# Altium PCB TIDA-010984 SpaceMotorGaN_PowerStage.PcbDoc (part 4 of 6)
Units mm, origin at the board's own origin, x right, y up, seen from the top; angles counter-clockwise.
Board outline 177.8 x 152.4 mm, 8 copper layers (Top Layer, DC LINK Layer 2, GND Layer 3, 3V3 Layer 4, Layer 5, Layer 6, GND Layer 7, Bottom Layer), stack 1.554 mm thick; 582 components, 280 nets, 1847 pads, 979 vias.
Unrouted connection lines stored in the file: 474.
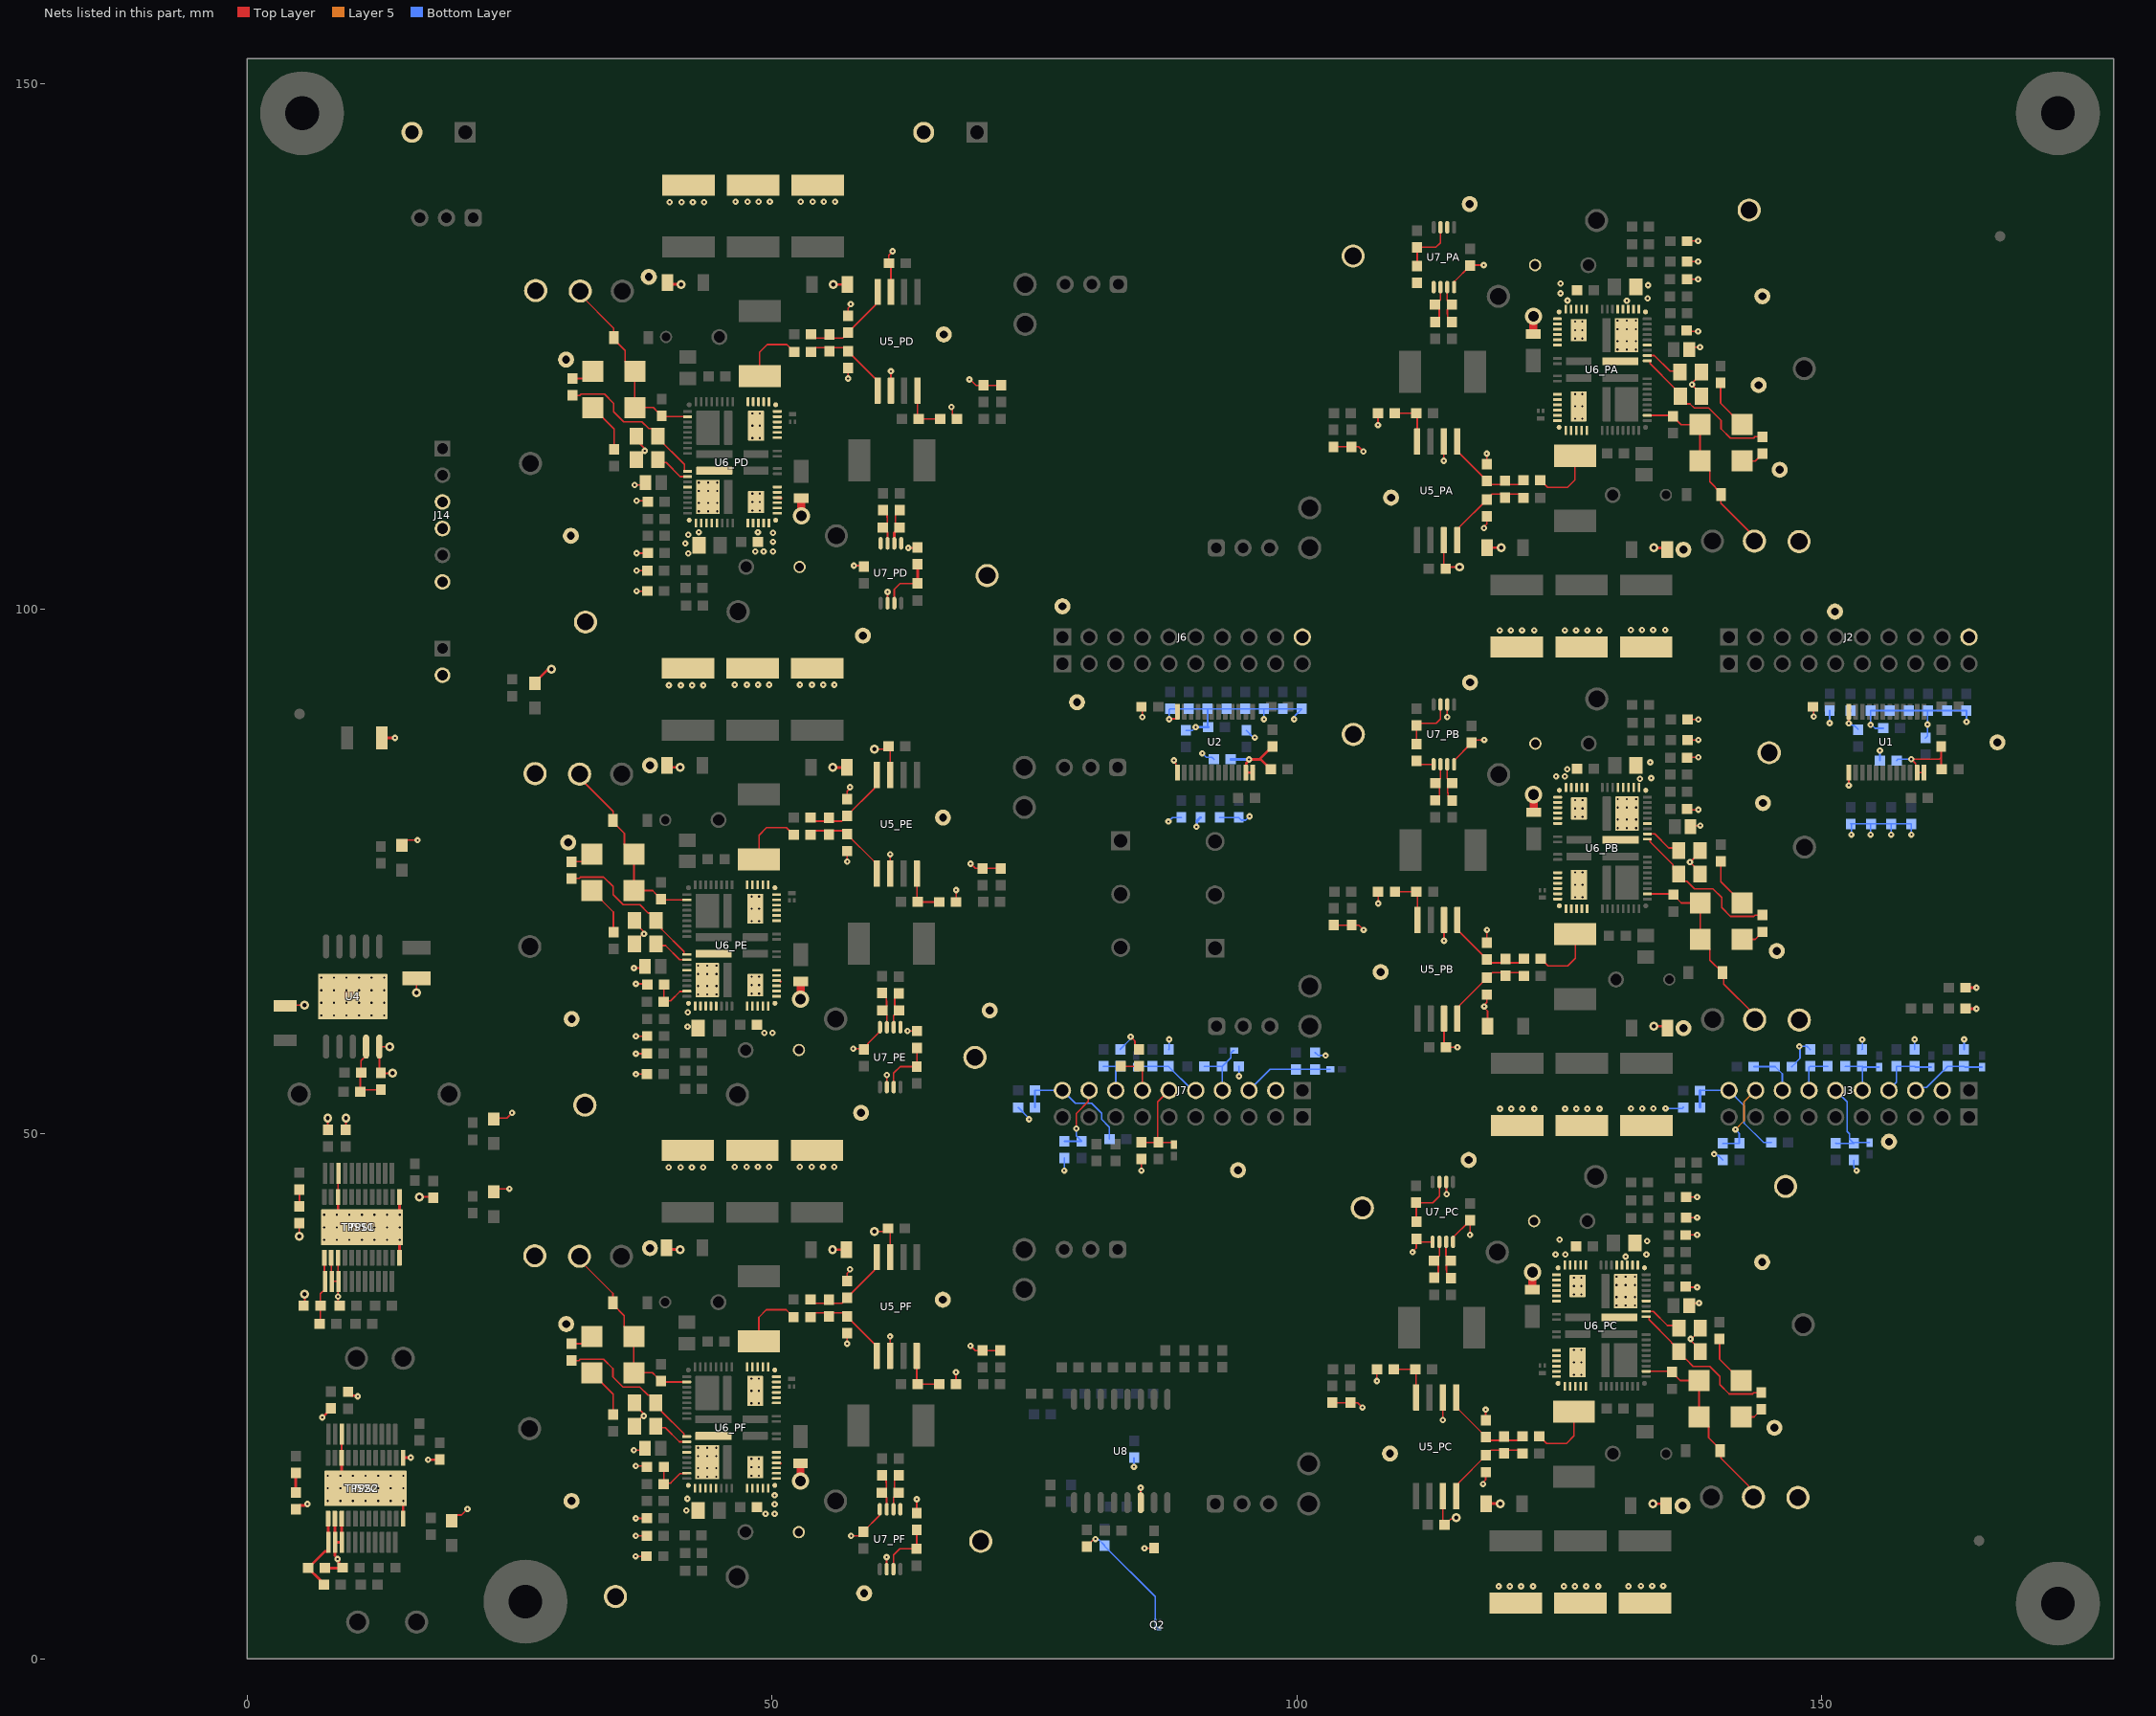
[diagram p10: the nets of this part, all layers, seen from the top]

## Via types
v1: diameter 0.61, hole 0.2, Top Layer to Bottom Layer, tented both sides, 306 vias
v2: diameter 0.61, hole 0.203, Top Layer to Bottom Layer, tented both sides, 272 vias
v3: diameter 0.5, hole 0.2, Top Layer to Bottom Layer, tented both sides, 216 vias
v4: diameter 0.5, hole 0.2, Top Layer to Bottom Layer, 66 vias
v5: diameter 0.61, hole 0.2, Top Layer to Bottom Layer, 61 vias
v6: diameter 0.864, hole 0.406, Top Layer to Bottom Layer, tented both sides, 17 vias
v7: diameter 1.651, hole 1.016, Top Layer to Bottom Layer, tented both sides, 12 vias
v8: diameter 0.864, hole 0.406, Top Layer to Bottom Layer, 9 vias
v9: diameter 0.61, hole 0.203, Top Layer to Bottom Layer, 8 vias
v10: diameter 1.27, hole 0.711, Top Layer to Bottom Layer, tented both sides, 5 vias
v11: diameter 0.61, hole 0.2, Top Layer to Bottom Layer, tented top, 2 vias
v12: diameter 1.651, hole 1.016, Top Layer to Bottom Layer, 2 vias
v13: diameter 0.61, hole 0.203, Top Layer to Bottom Layer, tented bottom, 1 vias
v14: diameter 1.27, hole 0.711, Top Layer to Bottom Layer, 1 vias
v15: diameter 1.651, hole 1.016, Top Layer to Bottom Layer, tented top, 1 vias

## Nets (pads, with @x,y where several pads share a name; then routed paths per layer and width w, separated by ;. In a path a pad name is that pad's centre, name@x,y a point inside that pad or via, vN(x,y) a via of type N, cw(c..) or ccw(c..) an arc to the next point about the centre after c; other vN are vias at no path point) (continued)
EN_HI_PE: C48_PE.1 R82_PE.1 U6_PE.18 | length 4.3
  Top Layer w0.152: C48_PE.1@39.723,64.204 R82_PE.1@39.723,62.592 ; R82_PE.1@39.732,62.576 R82_PE.1@39.707,62.576 R82_PE.1@39.723,62.592 ; U6_PE.18@41.898,63.597 41.866,63.566 41.244,63.566 40.4,62.722 40.4,62.665 39.795,62.665 R82_PE.1@39.723,62.592
EN_HI_PF: C48_PF.1 R82_PF.1 U6_PF.18 | length 4.3
  Top Layer w0.152: C48_PF.1@39.709,18.28 R82_PF.1@39.709,16.668 ; R82_PF.1@39.718,16.652 R82_PF.1@39.693,16.652 R82_PF.1@39.709,16.668 ; U6_PF.18@41.884,17.673 41.853,17.642 41.23,17.642 40.387,16.798 40.387,16.74 39.781,16.74 R82_PF.1@39.709,16.668
FB3: R69.1 R71.2 TPS2.13 TPS2C.12 | length 7.9
  Top Layer w0.254: R71.2@5.804,8.646 R71.2@5.829,8.646 ; R69.1@7.327,7.069 7.302,7.069 6.954,7.417 6.954,7.52 R71.2@5.829,8.646 ; TPS2.13@7.717,13.34 7.726,13.331 7.726,10.303 7.645,10.222 7.405,10.222 R71.2@5.829,8.646
FB5: R61.1 R63.2 TPS1.13 TPS1C.12 | length 6.5
  Top Layer w0.152: R61.1@6.912,31.892 6.988,31.969 R63.2@6.988,33.642 6.988,34.772 7.387,35.171 7.387,35.953 7.377,35.963 7.377,38.189 TPS1.13@7.368,38.198
GND: C1.2 C2.2 C3.2 C4.2 C5.2 C6.2 C7.2 C8.2 C9.2 C10.2 C11.2 C12.2 C13.2 C14.2 C15.2 C16.2 C17.2 C18.2 C19.2 C20.2 C22.2 C23.2 C24.2 C25.2 C27.2 C28.2 C30.2 C31_PA.2 C31_PB.2 C31_PC.2 C31_PD.2 C31_PE.2 C31_PF.2 C35_PA.2 C35_PB.2 C35_PC.2 C35_PD.2 C35_PE.2 C35_PF.2 C36_PA.2 C36_PB.2 C36_PC.2 C36_PD.2 C36_PE.2 C36_PF.2 C37_PA.1 C37_PB.1 C37_PC.1 C37_PD.1 C37_PE.1 C37_PF.1 C38_PA.2 C38_PB.2 C38_PC.2 C38_PD.2 C38_PE.2 C38_PF.2 C39_PA.2 C39_PB.2 C39_PC.2 C39_PD.2 C39_PE.2 C39_PF.2 C40_PA.2 C40_PB.2 C40_PC.2 C40_PD.2 C40_PE.2 C40_PF.2 C42_PA.2 C42_PB.2 C42_PC.2 C42_PD.2 C42_PE.2 C42_PF.2 C43_PA.2 C43_PB.2 C43_PC.2 C43_PD.2 C43_PE.2 C43_PF.2 C44_PA.1 C44_PB.1 C44_PC.1 C44_PD.1 C44_PE.1 C44_PF.1 C46_PA.1 C46_PB.1 C46_PC.1 C46_PD.1 C46_PE.1 C46_PF.1 C48_PA.2 C48_PB.2 C48_PC.2 C48_PD.2 C48_PE.2 C48_PF.2 C49_PA.2 C49_PB.2 C49_PC.2 C49_PD.2 C49_PE.2 C49_PF.2 C50_PA.1 C50_PB.1 C50_PC.1 C50_PD.1 C50_PE.1 C50_PF.1 C51_PA.1 C51_PB.1 C51_PC.1 C51_PD.1 C51_PE.1 C51_PF.1 C52_PA.1 C52_PB.1 C52_PC.1 C52_PD.1 C52_PE.1 C52_PF.1 C53_PA.2 C53_PB.2 C53_PC.2 C53_PD.2 C53_PE.2 C53_PF.2 C56_PA.1 C56_PB.1 C56_PC.1 C56_PD.1 C56_PE.1 C56_PF.1 C57.1 C61.2 D10.2 D12.2 D13.2 D14.2 D15_PA.2 D15_PB.2 D15_PC.2 D15_PD.2 D15_PE.2 D15_PF.2 D17.2 J2.10 J3.2 J6.10 J7.2 J11.2 J13.2 J14.3 J14.4 J14.6 J15.2 pad.8 pad.9 pad.10 pad.11 pad.12 pad.13 R13.1 R15.1 R16.1 R17.1 R18.1 R19.1 R20.1 R21.1 R22.1 R23.1 R24.1 R25.1 R26.1 R27.1 R28.1 R39.1 R40.1 R41.1 R42.1 R43.1 R44.1 R45.1 R46.1 R47.1 R48.1 R49.1 R50.1 R51.1 R52.1 R53.1 R57.1 R58.1 R60.1 R62.1 R63.1 R66.1 R68.1 R70.1 R71.1 R74.1 R86_PA.2 R86_PB.2 R86_PC.2 R86_PD.2 R86_PE.2 R86_PF.2 R91_PA.2 R91_PB.2 R91_PC.2 R91_PD.2 R91_PE.2 R91_PF.2 R92_PA.1 R92_PB.1 R92_PC.1 R92_PD.1 R92_PE.1 R92_PF.1 R95_PA.1 R95_PB.1 R95_PC.1 R95_PD.1 R95_PE.1 R95_PF.1 R100.2 TP14_PA.2 TP14_PB.2 TP14_PC.2 TP14_PD.2 TP14_PE.2 TP14_PF.2 TP16_PA.1 TP16_PB.1 TP16_PC.1 TP16_PD.1 TP16_PE.1 TP16_PF.1 TP17_PA.1 TP17_PB.1 TP17_PC.1 TP17_PD.1 TP17_PE.1 TP17_PF.1 TP18_PA.1 TP18_PB.1 TP18_PC.1 TP18_PD.1 TP18_PE.1 TP18_PF.1 TPS1.1 TPS1.10 TPS1.14 TPS1.15 TPS1.24 TPS1.25 TPS1C.9 TPS1C.13 TPS1C.14 TPS2.1 TPS2.10 TPS2.14 TPS2.15 TPS2.24 TPS2.25 TPS2C.9 TPS2C.13 TPS2C.14 U1.12 U1.13 U2.12 U2.13 U4.10 U4.11 U5_PA.2 U5_PA.7 U5_PB.2 U5_PB.7 U5_PC.2 U5_PC.7 U5_PD.2 U5_PD.7 U5_PE.2 U5_PE.7 U5_PF.2 U5_PF.7 U6_PA.14 U6_PA.20 U6_PA.21 U6_PA.22 U6_PA.23 U6_PA.24 U6_PA.25 U6_PA.29 U6_PA.30 U6_PA.31 U6_PA.32 U6_PA.33 U6_PA.34 U6_PA.35 U6_PA.36 U6_PA.37 U6_PA.38 U6_PA.39 U6_PA.40 U6_PA.67 U6_PA.68 U6_PA.70 U6_PB.14 U6_PB.20 U6_PB.21 U6_PB.22 U6_PB.23 U6_PB.24 U6_PB.25 U6_PB.29 U6_PB.30 U6_PB.31 U6_PB.32 U6_PB.33 U6_PB.34 U6_PB.35 U6_PB.36 U6_PB.37 U6_PB.38 U6_PB.39 U6_PB.40 U6_PB.67 U6_PB.68 U6_PB.70 U6_PC.14 U6_PC.20 U6_PC.21 U6_PC.22 U6_PC.23 U6_PC.24 U6_PC.25 U6_PC.29 U6_PC.30 U6_PC.31 U6_PC.32 U6_PC.33 U6_PC.34 U6_PC.35 U6_PC.36 U6_PC.37 U6_PC.38 U6_PC.39 U6_PC.40 U6_PC.67 U6_PC.68 U6_PC.70 U6_PD.14 U6_PD.20 U6_PD.21 U6_PD.22 U6_PD.23 U6_PD.24 U6_PD.25 U6_PD.29 U6_PD.30 U6_PD.31 U6_PD.32 U6_PD.33 U6_PD.34 U6_PD.35 U6_PD.36 U6_PD.37 U6_PD.38 U6_PD.39 U6_PD.40 U6_PD.67 U6_PD.68 U6_PD.70 U6_PE.14 U6_PE.20 U6_PE.21 U6_PE.22 U6_PE.23 U6_PE.24 U6_PE.25 U6_PE.29 U6_PE.30 U6_PE.31 U6_PE.32 U6_PE.33 U6_PE.34 U6_PE.35 U6_PE.36 U6_PE.37 U6_PE.38 U6_PE.39 U6_PE.40 U6_PE.67 U6_PE.68 U6_PE.70 U6_PF.14 U6_PF.20 U6_PF.21 U6_PF.22 U6_PF.23 U6_PF.24 U6_PF.25 U6_PF.29 U6_PF.30 U6_PF.31 U6_PF.32 U6_PF.33 U6_PF.34 U6_PF.35 U6_PF.36 U6_PF.37 U6_PF.38 U6_PF.39 U6_PF.40 U6_PF.67 U6_PF.68 U6_PF.70 U7_PA.1 U7_PA.4 U7_PA.6 U7_PB.1 U7_PB.4 U7_PB.6 U7_PC.1 U7_PC.4 U7_PC.6 U7_PD.1 U7_PD.4 U7_PD.6 U7_PE.1 U7_PE.4 U7_PE.6 U7_PF.1 U7_PF.4 U7_PF.6 U8.6 | length 336.2
  Top Layer w0.152: C30.2@3.626,62.206 3.671,62.25 v6(5.5,62.25) ; R62.1@4.997,41.498 4.973,41.475 v6(4.973,40.25) 5.062,40.338 v6@5.062,40.493 ; R63.1@5.388,33.642 5.5,33.754 v6(5.5,34.75) ; v6(7.69,51.5) 7.69,50.408 R60.1@7.712,50.386 ; TPS1.14@8.018,38.198 8.02,38.196 8.02,35.955 8.022,35.953 TPS1C.14@8.657,35.953 ; TPS1C.9@8.657,46.243 8.662,46.238 8.662,44.004 TPS1.10@8.668,43.998 ; TPS1.15@8.668,38.198 8.662,38.193 8.662,35.959 TPS1C.14@8.657,35.953 ; C22.2@8.808,33.642 8.662,33.788 v1(8.662,34.5) 8.66,34.503 8.66,35.951 TPS1C.14@8.657,35.953 ; TPS2C.9@9.006,21.385 9.011,21.38 9.011,19.146 TPS2.10@9.017,19.14 ; C20.2@9.402,50.386 9.422,50.406 v6(9.422,51.5) ; v6(13.587,58.306) U4.10@12.609,58.306 12.609,55.941 R74.1@12.75,55.8 12.78,55.77 v6(13.868,55.77) ; D10.2@14.75,77.472 14.75,77.499 15.224,77.973 v5(16.25,77.973) ; v6(16.142,63.436) C23.2@16.142,64.824 ; v6(16.429,43.998) 17.635,43.998 R58.1@17.725,43.908 ; D14.2@19.5,13.154 19.5,13.229 19.974,13.703 20.437,13.703 v5(21,14.265) ; D13.2@23.5,44.473 23.795,44.768 v5(25,44.768) ; D17.2@23.5,51.425 23.575,51.5 24.75,51.5 v5(25.25,52) ; v1(36.853,19.873) 37.863,19.873 C44_PF.1@37.87,19.88 ; v1(36.867,65.797) 37.877,65.797 C44_PE.1@37.884,65.804 ; C51_PF.1@36.87,22.174 36.87,22.295 37.708,23.133 v1(37.804,23.133) 37.717,23.221 37.717,23.414 36.898,24.233 C46_PF.1@36.87,24.233 ; C51_PE.1@36.884,68.098 36.884,68.219 37.722,69.058 v1(37.818,69.058) 37.731,69.145 37.731,69.338 36.912,70.157 C46_PE.1@36.884,70.157 ; v1(36.935,111.809) 37.945,111.809 C44_PD.1@37.952,111.816 ; C51_PD.1@36.952,114.11 36.952,114.231 37.791,115.07 v1(37.886,115.07) 37.799,115.157 37.799,115.35 36.98,116.169 C46_PD.1@36.952,116.169 ; v1(37.026,9.762) 38.051,9.762 R86_PF.2@38.065,9.777 ; v1(37.032,11.717) R91_PF.2@38.071,11.717 ; v1(37.032,13.374) 38.08,13.374 C49_PF.2@38.102,13.396 ; v1(37.032,18.367) 38.022,18.367 C48_PF.2@38.109,18.28 ; v1(37.04,55.687) 38.065,55.687 R86_PE.2@38.079,55.701 ; v1(37.046,57.641) R91_PE.2@38.085,57.641 ; v1(37.046,59.299) 38.094,59.299 C49_PE.2@38.116,59.32 ; v1(37.046,64.291) 38.036,64.291 C48_PE.2@38.123,64.204 ; v1(37.109,101.698) 38.133,101.698 R86_PD.2@38.148,101.713 ; v1(37.114,103.653) R91_PD.2@38.153,103.653 ; v1(37.114,105.31) 38.162,105.31 C49_PD.2@38.184,105.332 ; v1(37.114,110.303) 38.104,110.303 C48_PD.2@38.191,110.216 ; v1(57.168,30.017) C42_PF.2@57.168,31.014 ; C37_PF.1@57.168,35.976 57.168,36.715 57.433,36.981 v1(57.433,37.104) ; v1(57.182,75.941) C42_PE.2@57.182,76.938 ; C37_PE.1@57.182,81.901 57.182,82.64 57.447,82.905 v1(57.447,83.029) ; v1(57.25,121.953) C42_PD.2@57.25,122.95 ; C37_PD.1@57.25,127.913 57.25,128.652 57.515,128.917 v1(57.515,129.041) ; v5(57.545,11.717) 58.339,11.717 C50_PF.1@58.736,12.114 ; v1(57.75,58.109) 58.679,58.109 C50_PE.1@58.75,58.038 59.149,58.437 59.149,58.613 60.296,59.76 U7_PE.4@60.296,60.16 ; v1(57.818,104.121) 58.679,104.121 C50_PD.1@58.75,104.05 ; C50_PF.1@58.736,12.139 60.235,13.637 60.235,14.189 U7_PF.4@60.282,14.236 ; v6(59.763,40.711) 60.655,40.711 60.685,40.681 C31_PF.2@60.685,40.627 ; v6(59.777,86.635) 60.669,86.635 60.699,86.605 C31_PE.2@60.699,86.551 ; U7_PF.6@60.932,8.536 v9(60.932,9.682) ; U7_PE.6@60.946,54.46 v1(60.946,55.607) ; U7_PD.6@61.014,100.547 v1(61.014,101.619) ; C31_PF.2@61.079,40.996 61.257,40.818 U5_PF.7@61.257,38.262 ; C31_PE.2@61.093,86.92 61.271,86.742 U5_PE.7@61.271,84.186 ; C31_PD.2@61.161,132.932 61.148,132.946 61.148,133.674 61.5,134.026 v5(61.5,134.076) ; U5_PF.2@61.257,28.862 v1(61.257,30.707) ; U5_PE.2@61.271,74.786 v1(61.271,76.632) ; U5_PD.2@61.339,120.798 v1(61.339,122.644) ; U5_PD.7@61.339,130.198 C31_PD.2@61.339,132.754 ; v1(62.921,59.8) C56_PE.1@63.811,59.8 ; v1(62.989,105.812) 63.818,105.812 C56_PD.1@63.879,105.873 ; C56_PF.1@63.797,13.876 v5(63.797,15.191) ; v5(67.108,119.241) 67.191,119.158 67.191,118.497 67.589,118.098 C43_PD.2@67.614,118.098 ; C43_PF.2@67.532,26.163 v1(67.532,27.293) ; C43_PE.2@67.546,72.088 v1(67.546,73.217) ; v1(68.918,29.812) 69.372,29.358 R92_PF.1@70.059,29.358 C53_PF.2@71.766,29.358 C53_PF.2@71.766,29.333 ; v1(68.932,75.736) 69.386,75.282 R92_PE.1@70.073,75.282 C53_PE.2@71.78,75.282 C53_PE.2@71.78,75.257 ; v11@69,121.748 69.454,121.294 R92_PD.1@70.141,121.294 C53_PD.2@71.848,121.294 C53_PD.2@71.848,121.269 ; v1(84.169,59.25) 84.586,58.833 84.586,58.435 C15.2@84.985,58.036 ; U8.6@85.138,14.873 v1(85.138,16.29) ; R51.1@85.2,90.682 85.296,90.586 v1(85.296,89.695) ; v1(85.207,46.5) C16.2@85.207,47.59 ; v1(85.5,10.53) 86.367,10.53 R100.2@86.408,10.571 ; v1(87.836,89.5) 87.881,89.546 88.492,89.546 88.641,89.695 U2.12@88.641,90.216 ; v1(88.307,85.574) 88.307,85.45 88.492,85.266 88.492,84.565 U2.13@88.641,84.416 ; C53_PC.2@103.402,24.419 C53_PC.2@103.402,24.394 R92_PC.1@105.109,24.394 105.796,24.394 v1(106.25,23.94) ; C53_PA.2@103.5,115.475 C53_PA.2@103.5,115.45 R92_PA.1@105.207,115.45 105.894,115.45 v1(106.348,114.996) ; C53_PB.2@103.522,69.906 C53_PB.2@103.522,69.881 R92_PB.1@105.229,69.881 105.916,69.881 v1(106.37,69.427) ; v1(107.636,26.459) C43_PC.2@107.636,27.59 ; v1(107.733,117.515) C43_PA.2@107.733,118.644 ; v1(107.756,71.946) C43_PB.2@107.756,73.077 ; v5(111.033,38.728) 111.033,38.765 111.391,39.124 C56_PC.1@111.391,40.016 111.694,39.713 U7_PC.1@112.936,39.713 ; C56_PB.1@111.403,85.518 111.721,85.199 U7_PB.1@113.034,85.199 ; U5_PC.7@113.911,15.49 113.911,12.934 C31_PC.2@114.089,12.756 ; v1(113.911,22.738) U5_PC.2@113.911,24.89 ; U5_PA.7@114.009,106.546 114.009,103.99 C31_PA.2@114.187,103.812 ; v1(114.009,114.1) U5_PA.2@114.009,115.946 ; U5_PB.7@114.031,60.977 114.031,58.421 C31_PB.2@114.209,58.243 v1(115.301,58.243) ; v1(114.031,68.397) U5_PB.2@114.031,70.377 ; U7_PC.6@114.236,45.413 114.26,45.389 114.26,44.274 v5(114.283,44.25) ; v5(114.334,89.695) U7_PB.6@114.334,90.899 ; C31_PC.2@114.483,13.125 114.66,13.302 115.045,13.302 v6(115.181,13.438) ; C31_PA.2@114.581,104.181 114.581,104.019 114.611,103.99 v6(115.503,103.99) ; U7_PC.4@114.886,39.713 114.886,40.124 C50_PC.1@116.5,41.738 ; U7_PB.4@114.984,85.199 114.984,85.567 116.642,87.224 C50_PB.1@116.642,87.249 116.914,87.522 v5(117.855,87.522) ; U7_PA.4@114.984,130.65 115.031,130.697 115.031,131.206 116.5,132.675 C50_PA.1@116.5,132.7 116.544,132.744 v5(117.817,132.744) ; v5(116.5,40.378) C50_PC.1@116.5,41.738 ; C50_PC.1@116.5,41.763 C50_PC.1@116.5,41.738 ; v1(117.735,16.648) 117.735,16.771 118,17.037 C37_PC.1@118,17.776 ; v1(117.833,107.703) 117.833,107.827 118.098,108.092 C37_PA.1@118.098,108.831 ; C42_PC.2@118,22.738 v1(118,23.735) ; C42_PA.2@118.098,113.794 v1(118.098,114.791) ; C37_PB.1@118.12,63.262 118.12,62.523 117.855,62.258 v1(117.855,62.134) 117.855,62.011 118.17,61.695 C36_PB.2@118.17,60.252 ; C42_PB.2@118.12,68.225 v1(118.12,69.427) ; C48_PC.2@137.059,35.472 137.146,35.385 v1(138.136,35.385) ; C49_PC.2@137.066,40.356 137.088,40.378 v1(138.136,40.378) ; R91_PC.2@137.097,42.035 v1(138.136,42.035) ; R86_PC.2@137.102,43.975 137.117,43.99 v1(138.141,43.99) ; C48_PA.2@137.157,126.528 137.244,126.441 v1(138.234,126.441) ; C49_PA.2@137.164,131.411 v1(138.234,131.411) ; C48_PB.2@137.179,80.959 137.266,80.872 v1(138.256,80.872) ; C49_PB.2@137.186,85.843 137.208,85.864 v1(138.256,85.864) ; R91_PA.2@137.195,133.091 v1(138.234,133.091) ; R86_PA.2@137.2,135.031 137.215,135.045 v1(138.234,135.045) ; R91_PB.2@137.217,87.522 v1(138.256,87.522) ; R86_PB.2@137.237,89.476 v1(138.262,89.476) ; C44_PC.1@137.298,33.872 137.305,33.879 v1(138.315,33.879) ; C44_PA.1@137.388,124.713 137.61,124.935 v1(138.413,124.935) ; C44_PB.1@137.418,79.359 137.425,79.366 v1(138.435,79.366) ; C46_PC.1@138.298,29.519 138.298,29.554 137.601,30.251 137.601,30.381 v1(137.514,30.469) 137.592,30.469 138.298,31.174 C51_PC.1@138.298,31.743 ; C46_PB.1@138.418,74.756 138.418,74.921 v1(137.458,75.881) 137.484,75.881 138.418,76.815 C51_PB.1@138.418,76.98 ; C46_PA.1@138.549,120.427 138.549,120.444 137.653,121.34 v1(137.653,121.377) 137.74,121.464 137.74,121.603 138.549,122.412 C51_PA.1@138.549,122.651 ; R26.1@149.168,90.682 149.25,90.6 v1(149.25,89.74) ; v1(152.591,83.192) U1.13@152.591,84.416 ; v1(152.591,89.112) U1.12@152.591,90.216
  Top Layer w0.254: R70.1@4.648,14.24 4.648,14.265 4.996,14.613 5.517,14.613 5.654,14.75 v1(5.75,14.75) ; v1(7.167,23) 7.188,23 8.004,23.816 R68.1@8.004,23.841 ; R71.1@7.404,8.646 9.083,8.646 8.748,8.981 8.748,9.287 8.631,9.404 v1(8.631,9.5) 8.631,9.553 8.371,9.813 TPS2C.13@8.371,11.095 ; TPS2.14@8.367,13.34 8.369,13.338 8.369,11.097 TPS2C.13@8.371,11.095 ; v4(8.543,42.298) 8.668,42.423 TPS1.10@8.668,43.998 ; v4(8.892,17.44) 9.017,17.565 TPS2.10@9.017,19.14 ; TPS2.15@9.017,13.34 9.011,13.335 9.011,11.101 9.006,11.095 TPS2C.13@8.371,11.095 ; C25.2@9.64,25.431 9.64,25.406 9.988,25.058 10.491,25.058 v1(10.549,25) ; C24.2@12.833,87.725 v1(14.089,87.725) ; TPS1.24@14.518,38.198 14.518,39.873 v4(14.543,39.898) ; TPS1.1@14.518,43.998 14.518,42.323 v4(14.543,42.298) ; TPS2.24@14.867,13.34 14.867,15.015 v4(14.892,15.04) ; TPS2.1@14.867,19.14 14.887,19.161 v1(15.592,19.161) ; v1(17.25,18.955) 18.331,18.955 R66.1@18.354,18.977 ; D12.2@27.432,92.913 27.432,92.988 28.577,94.133 28.883,94.133 v6(29,94.25) ; C35_PF.2@40.154,38.986 v8(41.26,38.986) ; C35_PE.2@40.168,84.911 v8(41.274,84.911) ; C35_PD.2@40.236,130.923 v8(41.342,130.923) ; U6_PF.38@50.434,18.673 50.73,18.673 U6_PF.38@50.798,18.605 ; U6_PE.38@50.448,64.597 50.744,64.597 U6_PE.38@50.812,64.529 ; U6_PD.38@50.516,110.609 50.812,110.609 U6_PD.38@50.88,110.541 ; v8(55.778,38.973) 57.105,38.973 C36_PF.2@57.118,38.986 ; v8(55.791,84.898) 57.119,84.898 C36_PE.2@57.132,84.911 ; v8(55.86,130.91) 57.187,130.91 C36_PD.2@57.2,130.923 ; C36_PC.2@118.05,14.766 118.063,14.779 v8(119.39,14.779) ; C36_PA.2@118.148,105.821 118.161,105.834 v6(119.488,105.834) ; v8(133.908,14.766) C35_PC.2@135.014,14.766 ; v6(134.006,105.821) C35_PA.2@135.112,105.821 ; v8(134.028,60.252) C35_PB.2@135.134,60.252 ; C19.2@163.712,61.926 v1(164.75,61.926) ; R57.1@163.712,63.928 v1(164.75,63.928)
  Top Layer w0.762: v7(52.721,16.921) D15_PF.2@52.721,18.605 ; v7(52.735,62.845) D15_PE.2@52.735,64.529 ; v7(52.803,108.857) D15_PD.2@52.803,110.541 ; D15_PC.2@122.447,35.147 v7(122.447,36.831) ; D15_PA.2@122.545,126.203 v7(122.545,127.887) ; D15_PB.2@122.567,80.634 v7(122.567,82.318)
  Bottom Layer w0.152: C28.2@73.45,52.5 73.475,52.5 74.5,51.475 v5(74.5,51.39) ; v1(77.848,46.5) C13.2@77.848,47.7 ; C14.2@83.181,58.036 83.181,58.061 84.169,59.049 v1(84.169,59.25) ; v1(84.5,18.29) C57.1@84.5,19.144 ; v1(87.77,79.75) 88.155,80.135 R49.1@89.009,80.135 ; C17.2@87.794,58.036 87.836,58.078 v1(87.836,59) ; v1@87.921,89.5 v1(87.836,89.5) 87.836,90.398 R53.1@87.921,90.484 R52.1@89.713,90.484 R44.1@91.505,90.484 ; R50.1@89.443,88.435 90.06,88.435 v1(90.376,88.75) ; R48.1@90.431,79.736 R48.1@90.83,80.135 ; v1(91,86.25) 91.377,85.873 91.913,85.873 C12.2@92.116,85.67 ; C11.2@91.566,88.75 91.505,88.811 R44.1@91.505,90.484 ; R47.1@92.651,80.135 R46.1@94.473,80.135 94.735,79.873 95.123,79.873 v1(95.5,80.25) ; C18.2@94.482,56.436 94.5,56.418 v1(94.5,55.5) ; R45.1@95.206,88.435 95.206,88.41 95.775,87.84 95.913,87.84 v1(96,87.753) ; v1(96.88,89.5) R41.1@96.88,90.484 ; v1(99.75,89.5) 99.837,89.587 99.837,89.833 100.463,90.459 R39.1@100.463,90.484 R40.1@98.672,90.484 R41.1@96.88,90.484 ; C61.2@101.75,57.749 102.037,57.462 v13(102.75,57.462) ; v1(135.139,52.425) 136.723,52.425 C3.2@136.824,52.526 ; v1(139.75,48.076) 139.874,48.076 140.031,47.919 140.171,47.919 140.57,47.52 C4.2@140.57,47.495 ; C5.2@147.146,56.406 147.171,56.406 147.569,56.805 147.569,56.83 147.938,57.199 147.938,58.263 v1(147.87,58.331) 148.608,58.331 C6.2@148.902,58.037 C6.2@148.902,58.012 ; v1(150.768,89.127) R27.1@150.768,90.333 ; R28.1@152.765,90.309 152.591,90.135 v1(152.591,89.112) 152.714,89.112 152.894,88.933 153.072,88.933 153.471,88.534 R25.1@153.471,88.509 ; v1(152.831,78.5) 152.831,79.466 R24.1@152.769,79.528 R23.1@154.696,79.528 ; C7.2@153.068,47.495 153.068,46.8 153.331,46.538 v1(153.331,46.5) ; C8.2@153.855,58.037 153.874,58.057 v1(153.874,58.981) ; v1(154.669,78.5) 154.669,79.501 R23.1@154.696,79.528 ; C2.2@155.541,85.553 155.552,85.564 v1(155.552,86.514) ; C1.2@155.871,88.636 155.093,88.636 154.768,88.961 v1(154.663,88.961) 154.663,90.299 R19.1@154.673,90.309 R18.1@156.498,90.309 R17.1@158.323,90.309 R16.1@160.148,90.309 ; v1(156.623,78.5) R22.1@156.623,79.528 ; v1(158.55,78.5) R21.1@158.55,79.528 R22.1@156.623,79.528 ; C9.2@158.855,58.037 v1(158.855,59) ; R20.1@159.889,87.709 160.086,87.906 v1(160.086,88.988) 160.086,90.248 R16.1@160.148,90.309 ; C10.2@163.57,58.037 v1(163.57,59) ; v1(163.797,89.25) R13.1@163.797,90.309 R15.1@161.972,90.309 R16.1@160.148,90.309 ; R44.1@91.505,90.484 R43.1@93.296,90.484 R42.1@95.088,90.484 R41.1@96.88,90.484 ; R23.1@154.696,79.528 R22.1@156.623,79.528
  Bottom Layer w0.254: v1(90.376,88.75) C11.2@91.566,88.75 ; v1(90.433,79.249) 90.482,79.298 90.482,79.787 R48.1@90.83,80.135
  other v2: 119.234,6.906 120.303,6.906 121.367,6.906 122.513,6.906 125.436,6.906 126.505,6.906 127.569,6.906 128.715,6.906 132.789,6.938 133.854,6.938 49.391,13.801 50.266,13.801 41.853,14.133 50.266,14.725 41.957,15.25 50.266,15.575 131.334,38.301 124.649,38.523 125.574,38.523 133.315,38.523 133.369,39.784 125.033,39.931 40.168,46.814 41.314,46.814 42.378,46.814 43.447,46.814 46.452,46.846 47.599,46.846 48.663,46.846 49.731,46.846 52.655,46.846 53.801,46.846 54.865,46.846 55.934,46.846 119.354,52.393 120.423,52.393 121.487,52.393 122.633,52.393 125.557,52.393 126.625,52.393 127.69,52.393 128.836,52.393 131.841,52.425 132.91,52.425 133.974,52.425 49.279,59.615 50.064,59.615 41.971,60.201 41.983,61.574 132.69,83.822 133.765,83.882 124.704,84.052 125.534,84.052 125.77,84.733 133.668,85.394 40.182,92.738 41.328,92.738 42.392,92.738 43.461,92.738 46.466,92.77 47.612,92.77 48.677,92.77 49.745,92.77 52.669,92.77 53.815,92.77 54.879,92.77 55.948,92.77 119.332,97.962 120.4,97.962 121.465,97.962 122.611,97.962 125.534,97.962 126.603,97.962 127.667,97.962 128.813,97.962 131.819,97.994 132.887,97.994 133.952,97.994 135.098,97.994 42.039,105.289 48.408,105.47 49.217,105.47 50.092,105.47 41.751,106.247 50.092,106.394 42.039,107.063 50.092,107.245 43.041,107.304 48.659,107.304 125.79,129.37 131.432,129.357 133.413,129.579 125.131,130.056 133.467,130.84 125.131,130.987 40.25,138.75 41.396,138.75 42.461,138.75 43.529,138.75 46.535,138.782 47.681,138.782 48.745,138.782 49.814,138.782 52.737,138.782 53.883,138.782 54.947,138.782 56.016,138.782
  other v3: 42.959,17.355 43.834,17.355 44.709,17.355 48.059,17.436 48.759,17.436 42.959,18.16 43.834,18.16 44.709,18.16 48.059,18.244 48.759,18.244 48.059,19.052 48.759,19.052 42.959,19.3 43.834,19.3 44.709,19.3 42.959,20.105 43.834,20.105 44.709,20.105 130.459,33.647 131.334,33.647 132.209,33.647 130.459,34.452 131.334,34.452 132.209,34.452 126.409,34.7 127.109,34.7 126.409,35.508 127.109,35.508 130.459,35.592 131.334,35.592 132.209,35.592 126.409,36.316 127.109,36.316 130.459,36.397 131.334,36.397 132.209,36.397 42.973,63.279 43.848,63.279 44.723,63.279 48.073,63.36 48.773,63.36 42.973,64.084 43.848,64.084 44.723,64.084 48.073,64.168 48.773,64.168 48.073,64.976 48.773,64.976 42.973,65.224 43.848,65.224 44.723,65.224 42.973,66.029 43.848,66.029 44.723,66.029 130.579,79.134 131.454,79.134 132.329,79.134 130.579,79.939 131.454,79.939 132.329,79.939 126.529,80.187 127.229,80.187 126.529,80.995 127.229,80.995 130.579,81.079 131.454,81.079 132.329,81.079 126.529,81.803 127.229,81.803 130.579,81.884 131.454,81.884 132.329,81.884 43.041,109.291 43.916,109.291 44.791,109.291 48.141,109.372 48.841,109.372 43.041,110.096 43.916,110.096 44.791,110.096 48.141,110.18 48.841,110.18 48.141,110.988 48.841,110.988 43.041,111.236 43.916,111.236 44.791,111.236 43.041,112.041 43.916,112.041 44.791,112.041 130.557,124.703 131.432,124.703 132.307,124.703 130.557,125.508 131.432,125.508 132.307,125.508 126.507,125.756 127.207,125.756 126.507,126.564 127.207,126.564 130.557,126.648 131.432,126.648 132.307,126.648 126.507,127.372 127.207,127.372 130.557,127.453 131.432,127.453 132.307,127.453
  other v4: 7.692,15.04 8.892,15.04 10.092,15.04 11.292,15.04 12.492,15.04 13.692,15.04 7.692,16.24 8.892,16.24 10.092,16.24 11.292,16.24 12.492,16.24 13.692,16.24 14.892,16.24 7.692,17.44 10.092,17.44 11.292,17.44 12.492,17.44 13.692,17.44 14.892,17.44 7.343,39.898 8.543,39.898 9.743,39.898 10.943,39.898 12.143,39.898 13.343,39.898 7.343,41.098 8.543,41.098 9.743,41.098 10.943,41.098 12.143,41.098 13.343,41.098 14.543,41.098 7.343,42.298 9.743,42.298 10.943,42.298 12.143,42.298 13.343,42.298 7.069,61.281 8.269,61.281 9.469,61.281 10.669,61.281 11.869,61.281 13.069,61.281 7.069,62.481 8.269,62.481 9.469,62.481 10.669,62.481 11.869,62.481 13.069,62.481 7.069,63.681 8.269,63.681 9.469,63.681 10.669,63.681 11.869,63.681 13.069,63.681 7.069,64.881 8.269,64.881 9.469,64.881 10.669,64.881 11.869,64.881 13.069,64.881
  other v9: 131.61,6.906 134.903,6.938
  other v11: 68.822,121.858
HVIN_PA: R76_PA.1 R77_PA.1 U6_PA.45 U6_PA.46 U6_PA.47 U6_PA.48 U6_PA.49 U6_PA.50 U6_PA.51 U6_PA.52 U6_PA.53 U6_PA.54 U6_PA.55 U6_PA.56 U6_PA.73 | length 6.2
  Top Layer w0.152: R77_PA.1@123.228,112.248 123.911,111.566 125.79,111.566 126.507,112.283 R76_PA.1@126.507,114.587
  other v3: 126.507,118.117 127.207,118.117 126.507,119.292 127.207,119.292 126.507,120.467 127.207,120.467
HVIN_PB: R76_PB.1 R77_PB.1 U6_PB.45 U6_PB.46 U6_PB.47 U6_PB.48 U6_PB.49 U6_PB.50 U6_PB.51 U6_PB.52 U6_PB.53 U6_PB.54 U6_PB.55 U6_PB.56 U6_PB.73 | length 6.2
  Top Layer w0.152: R77_PB.1@123.225,66.679 123.25,66.679 123.933,65.997 125.812,65.997 126.529,66.714 R76_PB.1@126.529,69.018
  other v3: 126.529,72.548 127.229,72.548 126.529,73.723 127.229,73.723 126.529,74.898 127.229,74.898
HVIN_PC: R76_PC.1 R77_PC.1 U6_PC.45 U6_PC.46 U6_PC.47 U6_PC.48 U6_PC.49 U6_PC.50 U6_PC.51 U6_PC.52 U6_PC.53 U6_PC.54 U6_PC.55 U6_PC.56 U6_PC.73 | length 6.2
  Top Layer w0.152: R77_PC.1@123.13,21.193 123.813,20.51 125.692,20.51 126.409,21.227 R76_PC.1@126.409,23.531
  other v3: 126.409,27.061 127.109,27.061 126.409,28.236 127.109,28.236 126.409,29.411 127.109,29.411
HVIN_PD: R76_PD.1 R77_PD.1 U6_PD.45 U6_PD.46 U6_PD.47 U6_PD.48 U6_PD.49 U6_PD.50 U6_PD.51 U6_PD.52 U6_PD.53 U6_PD.54 U6_PD.55 U6_PD.56 U6_PD.73 | length 6.2
  Top Layer w0.152: R76_PD.1@48.841,122.157 48.841,124.461 49.558,125.178 51.437,125.178 52.12,124.495 R77_PD.1@52.145,124.495
  other v3: 48.141,116.277 48.841,116.277 48.141,117.452 48.841,117.452 48.141,118.627 48.841,118.627
HVIN_PE: R76_PE.1 R77_PE.1 U6_PE.45 U6_PE.46 U6_PE.47 U6_PE.48 U6_PE.49 U6_PE.50 U6_PE.51 U6_PE.52 U6_PE.53 U6_PE.54 U6_PE.55 U6_PE.56 U6_PE.73 | length 6.2
  Top Layer w0.152: R76_PE.1@48.773,76.145 48.773,78.449 49.49,79.166 51.369,79.166 52.051,78.484 R77_PE.1@52.076,78.484
  other v3: 48.073,70.265 48.773,70.265 48.073,71.44 48.773,71.44 48.073,72.615 48.773,72.615
HVIN_PF: R76_PF.1 R77_PF.1 U6_PF.45 U6_PF.46 U6_PF.47 U6_PF.48 U6_PF.49 U6_PF.50 U6_PF.51 U6_PF.52 U6_PF.53 U6_PF.54 U6_PF.55 U6_PF.56 U6_PF.73 | length 6.2
  Top Layer w0.152: R76_PF.1@48.759,30.221 48.759,32.525 49.476,33.242 51.355,33.242 52.038,32.559 R77_PF.1@52.063,32.559
  other v3: 48.059,24.341 48.759,24.341 48.059,25.516 48.759,25.516 48.059,26.691 48.759,26.691
NetC2_1: C2.1 R1.2 R2.2 U1.23 U1.24 | length 9.2
  Top Layer w0.152: U1.24@159.741,84.416 U1.23@159.091,84.416 158.942,84.565 158.942,85.274 v1(158.531,85.685) 161.212,85.685 161.386,85.86 ; R2.2@161.119,84.416 R2.2@161.45,84.747 161.386,84.811 161.386,85.86 ; R1.2@161.386,86.909 161.386,85.86
  Bottom Layer w0.152: C2.1@157.141,85.553 157.273,85.685 v1(158.531,85.685)
NetC3_1: C3.1 J3.10 R12.2 R14.1 | length 11.4
  Bottom Layer w0.152: R12.2@138.424,54.123 138.443,54.142 J3.10@141.176,54.142 142.615,52.704 142.615,51.026 144.471,49.169 R14.1@145.2,49.169
  Bottom Layer w0.254: C3.1@138.424,52.526 R12.2@138.424,54.123
NetC4_1: C4.1 J3.9 R11.2 | length 7.6
  Layer 5 w0.152: v1(141.788,50.422) 142.615,51.249 142.615,53.041 J3.9@143.716,54.142
  Bottom Layer w0.152: C4.1@140.57,49.095 R11.2@142.157,49.095 142.157,50.036 141.788,50.405 v1(141.788,50.422)
NetC5_1: C5.1 J3.8 R10.2 | length 4.6
  Bottom Layer w0.152: R10.2@143.529,56.406 C5.1@145.546,56.406 145.571,56.406 146.256,55.721 J3.8@146.256,54.142
NetC6_1: C6.1 J3.7 R7.2 | length 4
  Bottom Layer w0.152: J3.7@148.796,54.142 148.796,56.331 C6.1@148.902,56.437 R7.2@150.583,56.437
NetC7_1: C7.1 D4.2 J3.6 R6.2 | length 9.1
  Bottom Layer w0.152: R6.2@151.336,49.12 R6.2@151.336,49.095 C7.1@153.068,49.095 ; J3.6@151.336,54.142 152.437,53.041 152.437,50.221 152.669,49.989 152.669,49.494 C7.1@153.068,49.095 ; D4.2@154.577,49.169 153.142,49.169 C7.1@153.068,49.095
NetC8_1: C8.1 D2.2 J3.5 R5.2 | length 5.6
  Bottom Layer w0.152: R5.2@152.242,56.437 C8.1@153.855,56.437 C8.1@153.876,56.416 ; J3.5@153.876,54.142 C8.1@153.876,56.416 ; D2.2@155.497,56.364 153.928,56.364 C8.1@153.876,56.416
NetC9_1: C9.1 D3.2 J3.4 R4.2 | length 5.9
  Bottom Layer w0.152: J3.4@156.416,54.142 156.416,54.241 157.112,54.937 R4.2@157.112,56.437 C9.1@158.855,56.437 158.928,56.364 D3.2@160.447,56.364
NetC10_1: C10.1 D1.2 J3.3 R3.2 | length 7.3
  Bottom Layer w0.152: J3.3@158.956,54.142 159.242,54.429 160.005,54.429 161.589,56.014 161.614,56.014 162.013,56.412 R3.2@162.013,56.437 C10.1@163.57,56.437 163.644,56.364 D1.2@165.29,56.364
NetC12_1: C12.1 R29.2 R30.2 U2.23 U2.24 | length 8.4
  Top Layer w0.254: U2.24@95.889,84.747 95.791,84.649 U2.24@95.791,84.416 U2.23@95.141,84.416 95.185,84.46 95.185,85.303 95.456,85.574 v1(95.456,85.67) 96.442,85.67 ; R30.2@97.529,84.747 97.504,84.747 96.581,85.67 96.442,85.67 ; R29.2@97.681,86.909 97.681,86.884 97.333,86.536 97.308,86.536 96.442,85.67
  Bottom Layer w0.254: C12.1@93.716,85.67 v1(95.456,85.67)
NetC13_1: C13.1 J7.9 R38.2 | length 7.2
  Top Layer w0.152: v1(79,50.5) 79,51.944 80.145,53.089 80.145,54.072 J7.9@80.216,54.142
  Bottom Layer w0.152: C13.1@77.848,49.3 R38.2@79.5,49.3 79.5,49.325 79,49.825 v1(79,50.5)
NetC14_1: C14.1 J7.8 R37.2 | length 4.1
  Bottom Layer w0.152: R37.2@81.58,56.436 C14.1@83.181,56.436 83.181,56.411 82.756,55.986 J7.8@82.756,54.142
NetC15_1: C15.1 J7.7 R34.2 | length 4.2
  Top Layer w0.152: R34.2@83.253,56.436 C15.1@84.985,56.436 85.296,56.126 J7.7@85.296,54.142
NetC16_1: C16.1 D7.2 J7.6 R33.2 | length 8.6
  Top Layer w0.152: C16.1@85.207,49.19 R33.2@86.819,49.19 ; J7.6@87.836,54.142 86.735,53.041 86.735,49.274 R33.2@86.819,49.19 ; D7.2@88.307,48.978 88.096,49.19 R33.2@86.819,49.19
NetC17_1: C17.1 D5.2 J7.5 R32.2 | length 6.6
  Bottom Layer w0.152: D5.2@84.709,56.362 84.782,56.436 R32.2@86.259,56.436 87.769,56.436 90.062,54.142 J7.5@90.376,54.142
NetC18_1: C18.1 D6.2 J7.4 R31.2 | length 6
  Bottom Layer w0.152: R31.2@91.176,56.436 C18.1@92.882,56.436 C18.1@92.907,56.436 ; J7.4@92.916,54.142 92.916,56.427 C18.1@92.907,56.436 ; D6.2@94.039,57.919 93.939,57.919 93.715,57.695 93.715,57.244 C18.1@92.907,56.436
NetC21_2: C21.2 R62.2 | length 1.6
  Top Layer w0.152: R62.2@4.997,43.098 C21.2@4.997,44.708
NetC26_2: C26.2 R70.2 | length 1.9
  Top Layer w0.254: R70.2@4.648,15.84 C26.2@4.648,17.69
NetC28_1: C28.1 J7.10 R109.2 R113.1 | length 11.7
  Bottom Layer w0.152: C28.1@75.05,52.5 R109.2@75.05,54.142 J7.10@77.676,54.142 78.908,52.91 80.465,52.91 81.411,51.965 81.411,51.39 82.15,50.651 R113.1@82.15,49.5
NetC29_2: C29.2 R73.1 R74.2 U4.9 | length 6.6
  Top Layer w0.152: U4.9@11.339,58.306 11.339,57.456 10.869,56.986 C29.2@10.869,55.847 10.792,55.77 R73.1@10.792,53.999 10.993,54.2 R74.2@12.75,54.2
NetC37_PA_2: C37_PA.2 C41_PA.1 R75_PA.2 U5_PA.8 | length 9.1
  Top Layer w0.152: U5_PA.8@115.279,106.546 115.503,106.77 115.503,107.811 118.098,110.406 C37_PA.2@118.098,110.431 118.098,110.456 118.497,110.855 118.522,110.855 118.605,110.938 119.848,110.938 120.009,110.777 120.171,110.938 121.258,110.938 R75_PA.2@121.603,110.594
NetC37_PB_2: C37_PB.2 C41_PB.1 R75_PB.2 U5_PB.8 | length 9.1
  Top Layer w0.152: U5_PB.8@115.301,60.977 115.525,61.201 115.525,62.242 118.12,64.837 C37_PB.2@118.12,64.862 118.12,64.887 118.519,65.286 118.544,65.286 118.627,65.369 119.87,65.369 120.032,65.208 120.193,65.369 121.281,65.369 R75_PB.2@121.625,65.025
NetC37_PC_2: C37_PC.2 C41_PC.1 R75_PC.2 U5_PC.8 | length 9.1
  Top Layer w0.152: U5_PC.8@115.181,15.49 115.405,15.714 115.405,16.755 118,19.351 C37_PC.2@118,19.376 118,19.401 118.399,19.799 118.424,19.799 118.507,19.883 119.75,19.883 119.911,19.721 120.073,19.883 121.16,19.883 R75_PC.2@121.505,19.538
NetC37_PD_2: C37_PD.2 C41_PD.1 R75_PD.2 U5_PD.8 | length 9.1
  Top Layer w0.152: R75_PD.2@53.745,126.15 54.09,125.805 55.177,125.805 55.339,125.967 55.5,125.805 56.743,125.805 56.826,125.889 56.851,125.889 57.25,126.288 C37_PD.2@57.25,126.313 57.25,126.338 59.845,128.933 59.845,129.974 U5_PD.8@60.069,130.198
NetC37_PE_2: C37_PE.2 C41_PE.1 R75_PE.2 U5_PE.8 | length 9.1
  Top Layer w0.152: R75_PE.2@53.676,80.138 54.021,79.794 55.109,79.794 55.27,79.955 55.432,79.794 56.675,79.794 56.758,79.877 56.783,79.877 57.182,80.276 C37_PE.2@57.182,80.301 57.182,80.326 59.777,82.921 59.777,83.962 U5_PE.8@60.001,84.186
NetC37_PF_2: C37_PF.2 C41_PF.1 R75_PF.2 U5_PF.8 | length 9.1
  Top Layer w0.152: R75_PF.2@53.663,34.214 54.007,33.869 55.095,33.869 55.257,34.031 55.418,33.869 56.661,33.869 56.744,33.952 56.769,33.952 57.168,34.351 C37_PF.2@57.168,34.376 57.168,34.401 59.763,36.996 59.763,38.038 U5_PF.8@59.987,38.262
NetC41_PA_2: C41_PA.2 C42_PA.1 R77_PA.2 U5_PA.1 | length 9.1
  Top Layer w0.152: U5_PA.1@115.279,115.946 115.279,114.996 115.503,114.772 115.544,114.772 118.098,112.219 C42_PA.1@118.098,112.194 118.436,111.856 119.488,111.856 C41_PA.2@119.848,112.216 120.208,111.856 121.211,111.856 R77_PA.2@121.603,112.248
NetC41_PB_2: C41_PB.2 C42_PB.1 R77_PB.2 U5_PB.1 | length 9.1
  Top Layer w0.152: U5_PB.1@115.301,70.377 115.301,69.427 115.525,69.203 115.567,69.203 118.12,66.65 C42_PB.1@118.12,66.625 118.458,66.287 119.511,66.287 C41_PB.2@119.87,66.647 120.23,66.287 121.233,66.287 R77_PB.2@121.625,66.679
NetC41_PC_2: C41_PC.2 C42_PC.1 R77_PC.2 U5_PC.1 | length 9.1
  Top Layer w0.152: U5_PC.1@115.181,24.89 115.181,23.94 115.405,23.717 115.447,23.717 118,21.163 C42_PC.1@118,21.138 118.338,20.8 119.39,20.8 C41_PC.2@119.75,21.16 120.11,20.8 121.113,20.8 R77_PC.2@121.505,21.193
NetC41_PD_2: C41_PD.2 C42_PD.1 R77_PD.2 U5_PD.1 | length 9.1
  Top Layer w0.152: R77_PD.2@53.745,124.495 54.137,124.888 55.14,124.888 C41_PD.2@55.5,124.528 55.86,124.888 56.912,124.888 C42_PD.1@57.25,124.55 57.25,124.525 59.803,121.972 59.845,121.972 60.069,121.748 U5_PD.1@60.069,120.798
NetC41_PE_2: C41_PE.2 C42_PE.1 R77_PE.2 U5_PE.1 | length 9.1
  Top Layer w0.152: R77_PE.2@53.676,78.484 54.069,78.876 55.072,78.876 C41_PE.2@55.432,78.516 55.791,78.876 56.844,78.876 C42_PE.1@57.182,78.538 57.182,78.513 59.735,75.96 59.777,75.96 60.001,75.736 U5_PE.1@60.001,74.786
NetC41_PF_2: C41_PF.2 C42_PF.1 R77_PF.2 U5_PF.1 | length 9.1
  Top Layer w0.152: R77_PF.2@53.663,32.559 54.055,32.952 55.058,32.952 C41_PF.2@55.418,32.592 55.778,32.952 56.83,32.952 C42_PF.1@57.168,32.614 57.168,32.589 59.721,30.035 59.763,30.035 59.987,29.812 U5_PF.1@59.987,28.862
NetC43_PA_1: C43_PA.1 R79_PA.1 U5_PA.4 | length 4.7
  Top Layer w0.152: C43_PA.1@109.333,118.644 R79_PA.1@111.381,118.644 ; U5_PA.4@111.469,115.946 R79_PA.1@111.469,118.556
NetC43_PB_1: C43_PB.1 R79_PB.1 U5_PB.4 | length 4.7
  Top Layer w0.152: C43_PB.1@109.356,73.077 R79_PB.1@111.403,73.075 ; U5_PB.4@111.491,70.377 R79_PB.1@111.491,72.987
NetC43_PC_1: C43_PC.1 R79_PC.1 U5_PC.4 | length 4.7
  Top Layer w0.152: C43_PC.1@109.236,27.59 R79_PC.1@111.283,27.589 ; U5_PC.4@111.371,24.89 R79_PC.1@111.371,27.5
NetC43_PD_1: C43_PD.1 R79_PD.1 U5_PD.4 | length 4.7
  Top Layer w0.152: R79_PD.1@63.879,118.188 U5_PD.4@63.879,120.798 ; R79_PD.1@63.967,118.1 C43_PD.1@66.014,118.1
NetC43_PE_1: C43_PE.1 R79_PE.1 U5_PE.4 | length 4.7
  Top Layer w0.152: R79_PE.1@63.811,72.176 U5_PE.4@63.811,74.786 ; R79_PE.1@63.899,72.088 C43_PE.1@65.946,72.088
NetC43_PF_1: C43_PF.1 R79_PF.1 U5_PF.4 | length 4.7
  Top Layer w0.152: R79_PF.1@63.797,26.252 U5_PF.4@63.797,28.862 ; R79_PF.1@63.885,26.163 C43_PF.1@65.932,26.163
NetC46_PA_2: C46_PA.2 R80_PA.2 U6_PA.11 | length 14.9
  Top Layer w0.152: U6_PA.11@133.382,123.635 133.597,123.635 133.646,123.586 133.646,123.37 135.975,121.041 135.975,120.821 C46_PA.2@136.534,120.262 136.534,120.097 137.093,119.538 137.464,119.538 137.869,119.133 139.23,119.133 140.413,117.95 140.413,117.169 141.299,116.283 143.527,116.283 143.647,116.403 R80_PA.2@144.348,116.403
NetC46_PB_2: C46_PB.2 R80_PB.2 U6_PB.11 | length 15
  Top Layer w0.152: U6_PB.11@133.404,78.066 133.62,78.066 133.668,78.017 133.668,77.801 135.827,75.642 135.827,75.189 136.945,74.072 137.155,74.072 137.885,73.342 139.639,73.342 140.48,72.501 140.48,71.555 141.321,70.715 143.55,70.715 143.669,70.834 R80_PB.2@144.37,70.834
NetC46_PC_2: C46_PC.2 R80_PC.2 U6_PC.11 | length 14.9
  Top Layer w0.152: U6_PC.11@133.284,32.579 133.499,32.579 133.548,32.53 133.548,32.314 135.707,30.156 135.707,30.078 135.809,29.976 135.844,29.976 136.266,29.554 136.266,29.223 136.961,28.528 137.092,28.528 137.765,27.855 139.354,27.855 140.315,26.895 140.315,26.113 141.201,25.228 143.43,25.228 143.549,25.347 R80_PC.2@144.25,25.347
NetC46_PD_2: C46_PD.2 R80_PD.2 U6_PD.11 | length 14.9
  Top Layer w0.152: R80_PD.2@31,120.341 31.701,120.341 31.82,120.46 34.049,120.46 34.935,119.575 34.935,118.793 35.896,117.833 37.485,117.833 37.611,117.833 38.273,117.171 38.578,117.171 39.137,116.612 C46_PD.2@39.137,116.447 ; C46_PD.2@39.137,116.282 41.667,113.751 41.667,113.158 41.716,113.109 U6_PD.11@41.966,113.109
NetC46_PE_2: C46_PE.2 R80_PE.2 U6_PE.11 | length 14.9
  Top Layer w0.152: R80_PE.2@30.932,74.329 31.633,74.329 31.752,74.448 33.981,74.448 34.867,73.563 34.867,72.782 35.827,71.821 37.417,71.821 38.211,71.027 38.393,71.027 38.916,70.504 38.916,70.157 38.944,70.157 39.51,69.59 39.51,69.485 41.633,67.362 41.633,67.146 41.682,67.097 U6_PE.11@41.898,67.097
NetC46_PF_2: C46_PF.2 R80_PF.2 U6_PF.11 | length 14.9
  Top Layer w0.152: R80_PF.2@30.918,28.405 31.619,28.405 31.738,28.524 33.967,28.524 34.853,27.638 34.853,26.857 35.814,25.896 37.403,25.896 38.197,25.103 38.379,25.103 38.902,24.58 38.902,24.233 38.93,24.233 39.497,23.666 39.497,23.56 41.62,21.437 41.62,21.222 41.668,21.173 U6_PF.11@41.884,21.173
NetC47_PA_1: C47_PA.1 D8_PA.1 D9_PA.1 D11_PA.1 TP8_PA.1 U6_PA.3 | length 18.5
  Top Layer w0.152: U6_PA.3@133.382,118.435 C47_PA.1@135.771,118.435 ; C47_PA.1@135.846,118.36 135.846,118.335 136.621,117.56 D8_PA.1@138.413,117.56 D9_PA.1@138.413,114.163 ; D9_PA.1@138.413,114.1 139.337,113.176 139.337,112.116 140.411,111.041 D11_PA.1@140.41,110.888 ; D11_PA.1@140.41,110.888 140.41,110.084 143.598,106.896 TP8_PA.1@143.598,106.46
NetC47_PB_1: C47_PB.1 D8_PB.1 D9_PB.1 D11_PB.1 TP8_PB.1 U6_PB.3 | length 18.5
  Top Layer w0.152: U6_PB.3@133.404,72.866 C47_PB.1@135.793,72.866 ; C47_PB.1@135.868,72.791 135.868,72.766 136.643,71.991 D8_PB.1@138.435,71.991 D9_PB.1@138.435,68.594 ; D9_PB.1@138.435,68.531 139.359,67.608 139.359,66.547 140.433,65.472 140.433,65.32 140.678,65.074 140.678,64.269 143.62,61.327 TP8_PB.1@143.62,60.891
NetC47_PC_1: C47_PC.1 D8_PC.1 D9_PC.1 D11_PC.1 TP8_PC.1 U6_PC.3 | length 18.5
  Top Layer w0.152: U6_PC.3@133.284,27.379 C47_PC.1@135.673,27.379 ; C47_PC.1@135.748,27.304 135.748,27.279 136.523,26.504 D8_PC.1@138.315,26.504 D9_PC.1@138.315,23.107 ; D9_PC.1@138.315,23.045 139.239,22.121 139.239,21.06 140.313,19.986 D11_PC.1@140.312,19.833 ; D11_PC.1@140.312,19.833 140.416,19.729 140.416,19.084 143.106,16.394 143.106,15.798 TP8_PC.1@143.5,15.404
NetC47_PD_1: C47_PD.1 D8_PD.1 D9_PD.1 D11_PD.1 TP8_PD.1 U6_PD.3 | length 18.6
  Top Layer w0.152: TP8_PD.1@31.75,130.284 31.75,129.921 34.937,126.734 34.937,125.703 36.011,124.628 36.011,123.567 D9_PD.1@36.935,122.644 ; D9_PD.1@36.935,122.581 D8_PD.1@36.935,119.184 38.702,119.184 C47_PD.1@39.078,118.808 ; U6_PD.3@41.966,118.309 39.577,118.309 C47_PD.1@39.502,118.384 39.502,118.409 C47_PD.1@39.103,118.808 ; C47_PD.1@39.078,118.808 C47_PD.1@39.103,118.808 ; C47_PD.1@39.078,118.808 C47_PD.1@39.103,118.808
NetC47_PE_1: C47_PE.1 D8_PE.1 D9_PE.1 D11_PE.1 TP8_PE.1 U6_PE.3 | length 18.6
  Top Layer w0.152: TP8_PE.1@31.682,84.272 31.682,83.909 34.869,80.722 34.869,79.691 35.943,78.616 35.943,77.555 D9_PE.1@36.867,76.632 ; D9_PE.1@36.867,76.569 D8_PE.1@36.867,73.172 38.634,73.172 39.01,72.796 39.035,72.796 39.434,72.397 C47_PE.1@39.434,72.372 39.509,72.297 U6_PE.3@41.898,72.297
NetC47_PF_1: C47_PF.1 D8_PF.1 D9_PF.1 D11_PF.1 TP8_PF.1 U6_PF.3 | length 18.6
  Top Layer w0.152: TP8_PF.1@31.668,38.348 31.668,37.985 34.855,34.798 34.855,33.766 35.929,32.692 35.929,31.631 D9_PF.1@36.853,30.707 ; D9_PF.1@36.853,30.645 D8_PF.1@36.853,27.248 38.62,27.248 38.996,26.872 39.021,26.872 39.42,26.473 C47_PF.1@39.42,26.448 39.495,26.373 U6_PF.3@41.884,26.373
NetC51_PA_2: C51_PA.2 U6_PA.12 | length 3.7
  Top Layer w0.152: U6_PA.12@133.382,124.135 134.076,124.135 135.559,122.651 C51_PA.2@136.517,122.651
NetC51_PB_2: C51_PB.2 U6_PB.12 | length 3.5
  Top Layer w0.152: U6_PB.12@133.404,78.566 134.098,78.566 135.433,77.23 C51_PB.2@136.386,77.23
NetC51_PC_2: C51_PC.2 U6_PC.12 | length 3.5
  Top Layer w0.152: U6_PC.12@133.284,33.079 133.978,33.079 135.313,31.743 C51_PC.2@136.266,31.743
NetC51_PD_2: C51_PD.2 U6_PD.12 | length 3.5
  Top Layer w0.152: C51_PD.2@38.984,113.945 39.937,113.945 41.272,112.609 U6_PD.12@41.966,112.609
NetC51_PE_2: C51_PE.2 U6_PE.12 | length 3.5
  Top Layer w0.152: C51_PE.2@38.916,67.933 39.868,67.933 41.204,66.597 U6_PE.12@41.898,66.597
NetC51_PF_2: C51_PF.2 U6_PF.12 | length 3.5
  Top Layer w0.152: C51_PF.2@38.902,22.009 39.855,22.009 41.19,20.673 U6_PF.12@41.884,20.673
NetC54_PA_1: C54_PA.1 R89_PA.2 U7_PA.3 | length 4.2
  Top Layer w0.152: U7_PA.3@114.334,130.65 114.334,129.402 C54_PA.1@114.755,128.981 ; C54_PA.1@114.53,129.23 C54_PA.1@114.78,128.981 C54_PA.1@114.755,128.981 ; R89_PA.2@114.78,127.325 114.381,127.724 114.381,128.034 114.348,128.067 114.348,128.549 114.356,128.557 114.356,128.582 C54_PA.1@114.755,128.981
NetC54_PA_2: C54_PA.2 R90_PA.2 U7_PA.2 | length 3.9
  Top Layer w0.152: R90_PA.2@113.18,127.338 113.579,127.737 113.579,128.582 C54_PA.2@113.18,128.981 113.205,128.981 113.68,129.456 113.684,129.456 U7_PA.2@113.684,130.65
NetC54_PB_1: C54_PB.1 R89_PB.2 U7_PB.3 | length 4
  Top Layer w0.152: U7_PB.3@114.334,85.199 114.334,83.855 114.777,83.412 114.378,83.013 114.378,82.988 114.37,82.98 114.37,82.498 114.403,82.465 114.403,82.155 R89_PB.2@114.802,81.756
NetC54_PB_2: C54_PB.2 R90_PB.2 U7_PB.2 | length 4
  Top Layer w0.152: R90_PB.2@113.202,81.769 113.601,82.168 113.601,83.013 C54_PB.2@113.202,83.412 113.227,83.412 113.684,83.869 U7_PB.2@113.684,85.199
NetC54_PC_1: C54_PC.1 R89_PC.2 U7_PC.3 | length 4.4
  Top Layer w0.152: U7_PC.3@114.236,39.713 114.209,39.686 114.209,38.398 114.258,38.349 114.258,38.324 C54_PC.1@114.657,37.925 ; C54_PC.1@114.432,38.175 C54_PC.1@114.682,37.925 C54_PC.1@114.657,37.925 ; R89_PC.2@114.682,36.269 114.283,36.668 114.283,36.978 114.25,37.012 114.25,37.493 114.258,37.501 114.258,37.526 C54_PC.1@114.657,37.925
NetC54_PC_2: C54_PC.2 R90_PC.2 U7_PC.2 | length 4
  Top Layer w0.152: R90_PC.2@113.082,36.282 113.481,36.681 113.481,37.526 C54_PC.2@113.082,37.925 113.107,37.925 113.586,38.404 U7_PC.2@113.586,39.713
NetC54_PD_1: C54_PD.1 R89_PD.2 U7_PD.3 | length 3.7
  Top Layer w0.152: R89_PD.2@60.568,109.419 60.967,109.02 60.967,108.71 61,108.677 61,108.195 60.992,108.187 60.992,108.162 60.593,107.763 61.014,107.342 U7_PD.3@61.014,106.247
NetC54_PD_2: C54_PD.2 R90_PD.2 U7_PD.2 | length 3.7
  Top Layer w0.152: C54_PD.2@62.168,107.763 61.769,108.162 61.769,109.007 R90_PD.2@62.168,109.406
  Top Layer w0.254: U7_PD.2@61.664,106.247 61.664,107.284 62.143,107.763 C54_PD.2@62.168,107.763
NetC54_PE_1: C54_PE.1 R89_PE.2 U7_PE.3 | length 3.8
  Top Layer w0.152: C54_PE.1@60.5,61.751 C54_PE.1@60.525,61.751 ; R89_PE.2@60.5,63.407 60.899,63.008 60.899,62.698 60.932,62.665 60.932,62.183 60.924,62.175 60.924,62.15 C54_PE.1@60.525,61.751 ; U7_PE.3@60.946,60.16 60.946,61.33 C54_PE.1@60.525,61.751
NetC54_PE_2: C54_PE.2 R90_PE.2 U7_PE.2 | length 3.8
  Top Layer w0.152: U7_PE.2@61.596,60.16 61.596,61.272 62.075,61.751 C54_PE.2@62.1,61.751 61.701,62.15 61.701,62.995 R90_PE.2@62.1,63.394
NetC54_PF_1: C54_PF.1 R89_PF.2 U7_PF.3 | length 4
  Top Layer w0.152: C54_PF.1@60.486,15.827 C54_PF.1@60.511,15.827 ; R89_PF.2@60.486,17.482 60.885,17.084 60.885,16.774 60.918,16.74 C54_PF.1@60.918,16.259 ; U7_PF.3@60.932,14.236 60.932,15.406 C54_PF.1@60.511,15.827 ; C54_PF.1@60.511,15.827 C54_PF.1@60.91,16.226 ; C54_PF.1@60.91,16.226 C54_PF.1@60.91,16.251 ; C54_PF.1@60.91,16.226 C54_PF.1@60.91,16.251 ; C54_PF.1@60.91,16.226 C54_PF.1@60.91,16.251 ; C54_PF.1@60.91,16.226 C54_PF.1@60.91,16.251 ; C54_PF.1@60.91,16.226 C54_PF.1@60.91,16.251 ; C54_PF.1@60.91,16.226 C54_PF.1@60.91,16.251 ; C54_PF.1@60.91,16.226 C54_PF.1@60.91,16.251 ; C54_PF.1@60.91,16.226 C54_PF.1@60.91,16.251 ; C54_PF.1@60.91,16.251 C54_PF.1@60.918,16.259 ; C54_PF.1@60.91,16.251 C54_PF.1@60.918,16.259 ; C54_PF.1@60.91,16.251 C54_PF.1@60.918,16.259 ; C54_PF.1@60.91,16.251 C54_PF.1@60.918,16.259 ; C54_PF.1@60.91,16.251 C54_PF.1@60.918,16.259 ; C54_PF.1@60.91,16.251 C54_PF.1@60.918,16.259 ; C54_PF.1@60.91,16.251 C54_PF.1@60.918,16.259 ; C54_PF.1@60.91,16.251 C54_PF.1@60.918,16.259
NetC54_PF_2: C54_PF.2 R90_PF.2 U7_PF.2 | length 3.8
  Top Layer w0.152: U7_PF.2@61.582,14.236 61.582,15.348 62.061,15.827 C54_PF.2@62.086,15.827 61.687,16.226 61.687,17.071 R90_PF.2@62.086,17.469
NetC56_PA_2: C56_PA.2 R94_PA.2 U7_PA.7 | length 5.6
  Top Layer w0.152: C56_PA.2@111.469,132.672 R94_PA.2@111.469,134.45 113.26,134.45 113.684,134.874 U7_PA.7@113.684,136.35
NetC56_PB_2: C56_PB.2 R94_PB.2 U7_PB.7 | length 5.7
  Top Layer w0.152: C56_PB.2@111.403,87.118 R94_PB.2@111.403,88.895 111.622,89.114 113.275,89.114 113.684,89.523 U7_PB.7@113.684,90.899
NetC56_PC_2: C56_PC.2 R94_PC.2 U7_PC.7 | length 5.6
  Top Layer w0.152: C56_PC.2@111.391,41.616 111.391,43.45 112.958,43.45 113.586,44.078 U7_PC.7@113.586,45.413
NetC56_PD_2: C56_PD.2 R94_PD.2 U7_PD.7 | length 5.6
  Top Layer w0.152: U7_PD.7@61.664,100.547 61.664,101.883 62.199,102.419 R94_PD.2@63.879,102.419
  Top Layer w0.254: R94_PD.2@63.879,102.419 C56_PD.2@63.879,104.273
NetC56_PE_2: C56_PE.2 R94_PE.2 U7_PE.7 | length 5.6
  Top Layer w0.152: U7_PE.7@61.596,54.46 61.596,55.778 62.224,56.407 R94_PE.2@63.797,56.407 63.811,56.42 C56_PE.2@63.811,58.2
NetC56_PF_2: C56_PF.2 R94_PF.2 U7_PF.7 | length 5.6
  Top Layer w0.152: U7_PF.7@61.582,8.536 61.582,9.876 62.189,10.482 R94_PF.2@63.783,10.482 63.797,10.496 C56_PF.2@63.797,12.276
NetC59_2: C59.2 Q2.1 Q2.3 R107.2 | length 12.3
  Top Layer w0.152: R107.2@80,10.7 80,10.725 80.594,11.319 80.74,11.319 v1(80.827,11.406)
  Bottom Layer w0.152: v1(80.827,11.406) 80.915,11.319 81.17,11.319 81.7,10.789 C59.2@81.7,10.764 81.7,10.739 86.525,5.914 Q2.1@86.525,3.6 86.525,3.024 86.649,2.9 Q2.3@86.75,2.9
NetC61_1: C61.1 D16.2 J7.3 R72.2 | length 8.6
  Bottom Layer w0.152: J7.3@95.456,54.142 97.462,56.149 R72.2@99.925,56.149 C61.1@101.75,56.149 D16.2@103.2,56.149
NetD8_PA_2: D8_PA.2 R78_PA.1 | length 4.8
  Top Layer w0.152: R78_PA.1@140.374,121.524 140.374,119.599 D8_PA.2@142.413,117.56
NetD8_PB_2: D8_PB.2 R78_PB.1 | length 4.8
  Top Layer w0.152: R78_PB.1@140.396,75.955 140.396,74.03 D8_PB.2@142.435,71.991
NetD8_PC_2: D8_PC.2 R78_PC.1 | length 4.8
  Top Layer w0.152: R78_PC.1@140.276,30.469 140.276,28.543 D8_PC.2@142.315,26.504
NetD8_PD_2: D8_PD.2 R78_PD.1 | length 4.8
  Top Layer w0.152: D8_PD.2@32.935,119.184 34.974,117.145 R78_PD.1@34.974,115.219
NetD8_PE_2: D8_PE.2 R78_PE.1 | length 4.8
  Top Layer w0.152: D8_PE.2@32.867,73.172 34.906,71.133 R78_PE.1@34.906,69.208
NetD8_PF_2: D8_PF.2 R78_PF.1 | length 4.8
  Top Layer w0.152: D8_PF.2@32.853,27.248 34.892,25.209 R78_PF.1@34.892,23.283
NetD9_PA_2: D9_PA.2 R80_PA.1 | length 2.2
  Top Layer w0.152: D9_PA.2@142.413,114.1 143.67,114.1 144.348,114.778 R80_PA.1@144.348,114.803
NetD9_PB_2: D9_PB.2 R80_PB.1 | length 2.2
  Top Layer w0.152: D9_PB.2@142.435,68.531 143.693,68.531 144.37,69.209 R80_PB.1@144.37,69.234
NetD9_PC_2: D9_PC.2 R80_PC.1 | length 2.2
  Top Layer w0.152: D9_PC.2@142.315,23.045 143.572,23.045 144.25,23.722 R80_PC.1@144.25,23.747
NetD9_PD_2: D9_PD.2 R80_PD.1 | length 2.2
  Top Layer w0.152: R80_PD.1@31,121.941 32.232,121.941 D9_PD.2@32.935,122.644
NetD9_PE_2: D9_PE.2 R80_PE.1 | length 2.2
  Top Layer w0.152: R80_PE.1@30.932,75.929 32.164,75.929 D9_PE.2@32.867,76.632
NetD9_PF_2: D9_PF.2 R80_PF.1 | length 2.2
  Top Layer w0.152: R80_PF.1@30.918,30.005 32.15,30.005 D9_PF.2@32.853,30.707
